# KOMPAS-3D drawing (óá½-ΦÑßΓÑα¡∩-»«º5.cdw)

Referenced files: вал-шестерня.cdw
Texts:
  Вал-шестерня
  Noncommercial version
  Модуль нормальный
  Число зубьев
  Угол наклона зуба
  Symbol type A
  Направление зуба
  правый
  Исходный контур
  ГОСТ 13755-81
  Коэффициент смещения
  исходного контура
  Степень точности
  по ГОСТ 1643-81
  Делительный диаметр
  Обозначение чертежа
  сопряженного колеса
  ОКМА.1001.
  1. Термообработка, улучшение НВ 230.
  2. Неуказанные предельные отклонения размеров:
  отверстий по Н14, валов по h14.
  3. Острые кромки притупить R   0,3.
  Ra1.25
  Ra3.2
  Ra0.63
  Ra6.3
  Сталь 45  ГОСТ 1050-88
  ДГТУ
Dimensions and other numbers on the sheet: 0; 2; 34; 10 51'; 8-С; 69.236; 0100.06; 73,24; 45; 0,04; 35; 12; 0.025; 178; 16; 142,9; 93,1; 86; 50; 5; 1; 2 фаски; 0,08; 1,5; 40; 0,03; 0,005; 1:1; 3.68; 3; 4; 6; 7; 8; 9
